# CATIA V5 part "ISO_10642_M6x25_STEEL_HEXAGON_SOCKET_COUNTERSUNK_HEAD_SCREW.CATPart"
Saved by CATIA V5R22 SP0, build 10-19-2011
Part number: ISO 10642 SCREW M6x25 STEEL HEXAGON SOCKET COUNTERSUNK HEAD
Publications: "Mating Edge", "Axis"
Bounding box of the stored display mesh (mm): x -25.42 to 0, y -6.719 to 6.719, z -6.714 to 6.714
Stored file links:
  D:\PER\CAO_PER_MODIF_2025\CAO_PER_pick&place_2024P\Sous_Ensemble_Flacon\ISO_10642_M6x25_STEEL_HEXAGON_SOCKET_COUNTERSUNK_HEAD_SCREW.CATPart
  C:\Program Files\Dassault Systemes\B22\win_b64\startup\components\MechanicalStandardParts\EN_Standards\Design_Tables\EN_ISO_10642_HEXAGON_SOCKET_COUNTERSUNK_SCREW.txt
  C:\Program Files\Dassault Systemes\B22\win_b64\startup\components\MechanicalStandardParts\ISO_Standards\Design_Tables\ISO_10642_HEXAGON_SOCKET_COUNTERSUNK_SCREW.txt
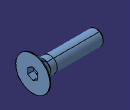
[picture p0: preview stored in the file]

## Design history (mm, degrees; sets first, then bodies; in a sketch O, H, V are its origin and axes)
Parameters
  l_length_nom = 25 mm
  b_ref = 24
  l_length_min = 24.58 mm
  l_length_max = 25.42 mm
  dk_head_dia_max = 13.44 mm
  dk_head_dia_min = 11.34 mm
  ls = 6.72 mm
  k_hed_depth = 3.72 mm
  r = 0.25 mm
  s_across_flats = 4 mm
  t_insert_depth = 2.2 mm
  d_dia = 6 mm
  threading = 18.28 mm
  p_pitch = 1 mm
Body1 "PartBody" (main body)
  Sketch1 on zx-plane, origin (0, 0, 0), H (-1, 0, 0), V (0, 0, 1)
    line L1 (0, 6.72) -> (0.3333, 6.72)
    point P2 (0.3333, 6.72)
    line L2 (0.3333, 6.72) -> (4.0533, 3)
    line L3 (4.0533, 3) -> (6.72, 3)
    line L4 (6.72, 3) -> (6.72, 2.9268)
    point P5 (6.72, 2.9268)
    line L5 (6.72, 2.9268) -> (24.8787, 2.9268)
    point P6 (24.8787, 2.9268)
    line L6 (24.8787, 2.9268) -> (25.42, 2.3855)
    axis line L7 (-30, 0) -> (125, 0)
    line L8 (25.42, 2.3855) -> (25.42, 0)
    point P10 (25.42, 0)
    line L9 (0, 6.72) -> (0, 0)
    distance L9 P5 = 6.72 {= ls}
    distance L9 L8 = 25.42 {= l_length_max}
    angle L5 L6 = 45
    distance L5 L7 = 2.9268 {= d_dia /2.05}
    distance L3 L7 = 3 {= d_dia  /2}
    angle L7 L2 = 45
    distance L1 L7 = 6.72 {= dk_head_dia_max /2}
    distance L9 P2 = 0.3333 {= p_pitch /3}
    distance P6 L8 = 0.5413 {= p_pitch *0.5413}
    horizontal: L1 H, L3 H, L5 H, L7 H
    vertical: L4 V, L9 V
    fix: L7
    coincidence: P10 L7
  Shaft1: profile Sketch1, axis Sketch1.L7, angle 360
  Body2
    Sketch2 on face of Shaft1, origin (0, 0, 0), H (0, 1, 0), V (0, 0, 1)
      point P1 (2, -1.1547)
      point P2 (2, 1.1547)
      point P3 (0, 2.3094)
      point P4 (-2, 1.1547)
      point P5 (-2, -1.1547)
      point P6 (0, -2.3094)
      point P7 (2, 0)
      line L1 (2, -1.1547) -> (2, 1.1547)
      line L2 (2, 1.1547) -> (0, 2.3094)
      line L3 (0, 2.3094) -> (-2, 1.1547)
      line L4 (-2, 1.1547) -> (-2, -1.1547)
      line L5 (-2, -1.1547) -> (0, -2.3094)
      line L6 (0, -2.3094) -> (2, -1.1547)
      construction line L7 (0, 0) -> (2, 0)
      construction circle A1 centre (0, 0) radius 2.3094
      construction arc A2 centre (-2, -1.1547) radius 2.3094 from (-2, 1.1547) to (0, -2.3094) cw
      construction arc A3 centre (2, 1.1547) radius 2.3094 from (0, 2.3094) to (2, -1.1547) ccw
      point P8 (-2, -1.1547)
      point P9 (2, 1.1547)
      distance L1 L4 = 4 {= s_across_flats}
      horizontal: L7 H
      coincidence: A1 P1, A1 P2, A1 P3, A1 P4, A1 P5, A1 P6, A2 P4, A2 P6, A2 O, P8 P5, A3 P3, A3 P1, A3 O, P9 P2
      midpoint: P7 L1
    Pad1: profile Sketch2, direction (-1, 0, 0), length 20
    Body3
      Sketch3 on zx-plane, origin (0, 0, 0), H (-1, 0, 0), V (0, 0, 1)
        line L1 (0, 0) -> (0, 2.3094)
        line L2 (0, 2.3094) -> (2.2, 2.3094)
        point P2 (2.2, 2.3094)
        line L3 (2.2, 2.3094) -> (3.5333, 0)
        point P3 (3.5333, 0)
        axis line L4 (-13.9938, 0) -> (46.4324, 0)
        reference projected line E1 (0, 2.3094) -> (20, 2.3094) from edge [face of Pad1 | face of Pad1]
        angle L3 L4 = 60
        distance L1 P2 = 2.2 {= t_insert_depth}
        vertical: L1 V
        horizontal: L2 H, L4 H
        fix: L4
        coincidence: L2 E1, P3 L4
      Shaft2: profile Sketch3, axis Sketch3.L4, angle 360
    Intersect1: tool Body3
  Remove1: tool Body2
  Fillet1: radius 0.25 {= r}, on edge [face of Shaft1 | face of Shaft1]
  Thread1: diameter 5.8537 {= d_dia /1.025}, depth 18.28 {= threading}, pitch 1, on face of Shaft1, from face of Shaft1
